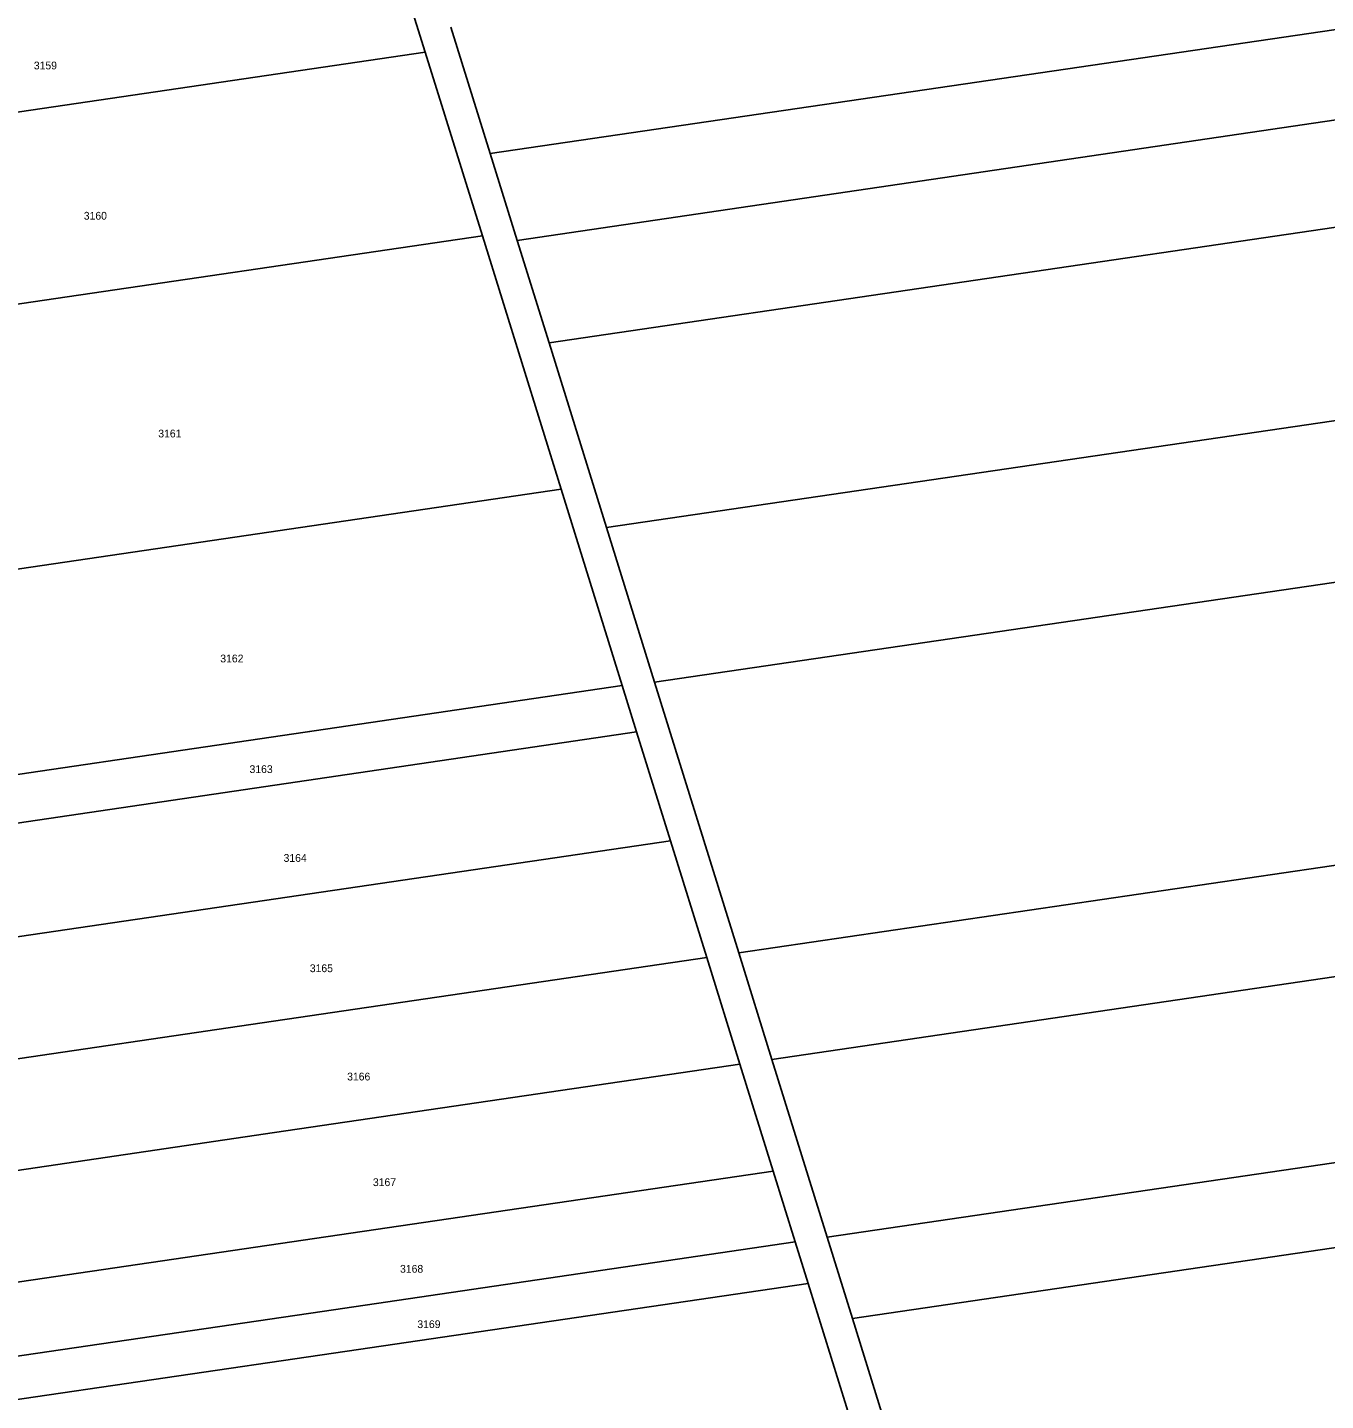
# Model space of a CAD drawing. Extents: x -618848 to -615803, y -1044450 to -1042254.
# Drawn here: x -616765.3 to -616481.6, y -1043345.1 to -1043045.1 of the extents above; entities that cross this region are included whole.
import ezdxf

# ---------------------------------------------------------------- set-up
doc = ezdxf.new("R2010")
doc.units = 0
doc.header["$LTSCALE"] = 0.68
doc.layers.add('1', color=7, linetype='Continuous', lineweight=25)
doc.layers.add('2', color=7, linetype='Continuous')

msp = doc.modelspace()

# ---------------------------------------------------------------- linework, layer by layer
at = {"layer": '1'}
for p, q in [((-616678.35, -1043050.51), (-616684.53, -1043030.63)), ((-616664.16, -1043072.65), (-616672.73, -1043045.02)), ((-616664.16, -1043072.65), (-616476.85, -1043045.15)), ((-616678.35, -1043050.51), (-616825.7, -1043072.18)), ((-616665.88, -1043090.61), (-616678.35, -1043050.51)), ((-616471, -1043064.05), (-616658.25, -1043091.61)), ((-616658.25, -1043091.61), (-616664.16, -1043072.65)), ((-616651.29, -1043114.01), (-616464.01, -1043086.49)), ((-616856.2, -1043118.59), (-616665.88, -1043090.61)), ((-616665.88, -1043090.61), (-616648.67, -1043145.97)), ((-616651.29, -1043114.01), (-616658.25, -1043091.61)), ((-616638.74, -1043154.37), (-616651.29, -1043114.01)), ((-616451.52, -1043126.85), (-616638.74, -1043154.37)), ((-616648.67, -1043145.97), (-616833.15, -1043173.1)), ((-616635.31, -1043188.92), (-616648.67, -1043145.97)), ((-616628.24, -1043188.16), (-616638.74, -1043154.37)), ((-616628.24, -1043188.16), (-616441.06, -1043160.65)), ((-616826.24, -1043216.98), (-616635.31, -1043188.92)), ((-616635.31, -1043188.92), (-616632.17, -1043199.04)), ((-616609.85, -1043247.32), (-616628.24, -1043188.16)), ((-616632.17, -1043199.04), (-616824.43, -1043227.31)), ((-616624.78, -1043222.81), (-616632.17, -1043199.04)), ((-616422.57, -1043219.8), (-616609.85, -1043247.32)), ((-616819.54, -1043251.45), (-616624.78, -1043222.81)), ((-616624.78, -1043222.81), (-616616.84, -1043248.35)), ((-616602.6, -1043270.62), (-616415.33, -1043243.1)), ((-616616.84, -1043248.35), (-616716.5, -1043263)), ((-616609.6, -1043271.65), (-616616.84, -1043248.35)), ((-616602.6, -1043270.62), (-616609.85, -1043247.32)), ((-616716.5, -1043263), (-616816.16, -1043277.65)), ((-616711.32, -1043286.6), (-616609.6, -1043271.65)), ((-616609.6, -1043271.65), (-616602.34, -1043295)), ((-616590.53, -1043309.43), (-616602.6, -1043270.62)), ((-616403.26, -1043281.91), (-616590.53, -1043309.43)), ((-616813.03, -1043301.56), (-616711.32, -1043286.6)), ((-616602.34, -1043295), (-616705.02, -1043310.1)), ((-616597.53, -1043310.46), (-616602.34, -1043295)), ((-616585, -1043327.2), (-616397.73, -1043299.68)), ((-616705.02, -1043310.1), (-616807.71, -1043325.2)), ((-616700.86, -1043325.65), (-616597.53, -1043310.46)), ((-616597.53, -1043310.46), (-616594.71, -1043319.53)), ((-616585, -1043327.2), (-616590.53, -1043309.43)), ((-616594.71, -1043319.53), (-616698.42, -1043334.78)), ((-616576.65, -1043377.61), (-616594.71, -1043319.53)), ((-616804.19, -1043340.84), (-616700.86, -1043325.65)), ((-616569.16, -1043378.16), (-616585, -1043327.2)), ((-616698.42, -1043334.78), (-616802.12, -1043350.03))]:
    msp.add_line(p, q, dxfattribs=at)

# ---------------------------------------------------------------- texts
at = {"layer": '2'}
for s, p in [('3159', (-616763.88, -1043054.245)), ('3160', (-616752.97, -1043087.085)), ('3161', (-616736.69, -1043134.675)), ('3162', (-616723.14, -1043183.835)), ('3163', (-616716.75, -1043208.015)), ('3164', (-616709.31, -1043227.425)), ('3165', (-616703.58, -1043251.525)), ('3166', (-616695.42, -1043275.195)), ('3167', (-616689.79, -1043298.275)), ('3168', (-616683.86, -1043317.205)), ('3169', (-616680.08, -1043329.305))]:
    msp.add_text(s, height=1.7, dxfattribs=at).set_placement(p)

doc.saveas('drawing.dxf')
